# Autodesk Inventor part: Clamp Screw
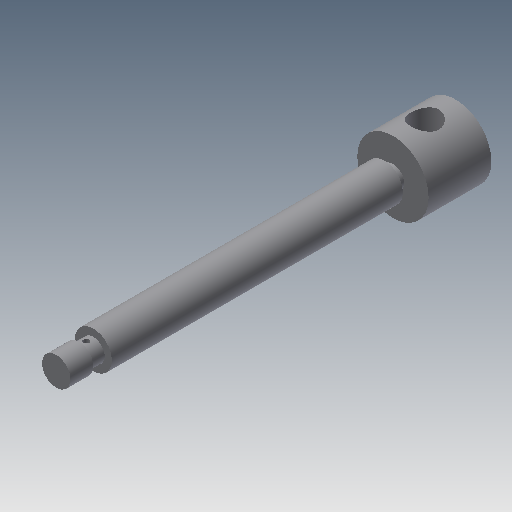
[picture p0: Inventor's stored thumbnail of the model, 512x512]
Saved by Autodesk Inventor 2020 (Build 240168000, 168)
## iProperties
Created: 2002-02
Part Number: Clamp Screw
Document SubType Name: Modeling
Designer: ***
Density: 1 g/cm^3
Material: Generic
Mass: 23.4442 g
Surface Area: 81.4176 cm^2
Volume: 23.4442 cm^3
Appearance: Default
Control State: 0
Master: False
Checked Out: False
Shininess: 77.0
Length Units: 11269
Angle Units: 11279
Time Units: 11290
Mass Units: 11283
Length Display Precision: 3
Angle Display Precision: 2
Density: 0.0
Volumn: 0.0
Area: 0.0
PropertySet Name: Model Information
Author: ***
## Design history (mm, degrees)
sketch "Sketch1"
  geometry: L1 (0, 140)-(5, 140); L2 (5, 140)-(5, 132); L3 (5, 132)-(4, 132); L4 (4, 132)-(4, 127); L5 (4, 127)-(6.5, 127); L6 (6.5, 127)-(6.5, 25); L7 (6.5, 25)-(4, 25); L8 (4, 25)-(4, 22); L9 (4, 22)-(12.5, 22); L10 (12.5, 22)-(12.5, 0); L11 (12.5, 0)-(0, 0); L12 (0, 0)-(0, 140)
  constraints: 24 end point, 10 parallel, 1 horizontal, 1 perpendicular
  dimensions: "d0" = 10 diameter of L2 L12; "d1" = 8 diameter of L4 L12; "d2" = 13 diameter of L6 L12; "d3" = 8 diameter of L7.end L12; "d4" = 25 diameter of L10 L12; "d5" = 3 distance from line of L7.end L9; "d6" = 8 distance of L1.end L2.end; "d7" = 13 vertical distance of L1.end L5.end; "d8" = 22 distance of L9.end L10.end; "d10" = 102 distance of L5.end L6.end
revolve "Revolution1" sketch "Sketch1" stored, may be unused: angle "d11" = 90 deg
sketch "Sketch3"
  geometry: L1 (-12.5, 0)-(12.5, 0) reference; C1 r 5 at (-0.113, 11)
  constraints: 1 centre point
  dimensions: "d13" = 10 diameter of C1; "d14" = 11 distance from line of L1 C1.centre
extrude "Extrusion1" cut sketch "Sketch3" extent not by distance; stored distance "d15" = 10; taper "d16" = 0 deg
sketch "Sketch4"
  geometry: L1 (0, 138.841)-(0, 0); L2 (-12.5, 0)-(12.5, 0) reference; L3 (-5, 140)-(5, 140) reference; C1 r 1 at (0, 129.5)
  constraints: 2 end point, 1 centre point, 1 point on line, 1 vertical
  dimensions: "d17" = 2 diameter of C1; "d18" = 10.5 distance from line of L3 C1.centre
extrude "Extrusion2" cut sketch "Sketch4" stored distance "d19" = 10; taper "d20" = 0 deg
body "Solid1"
